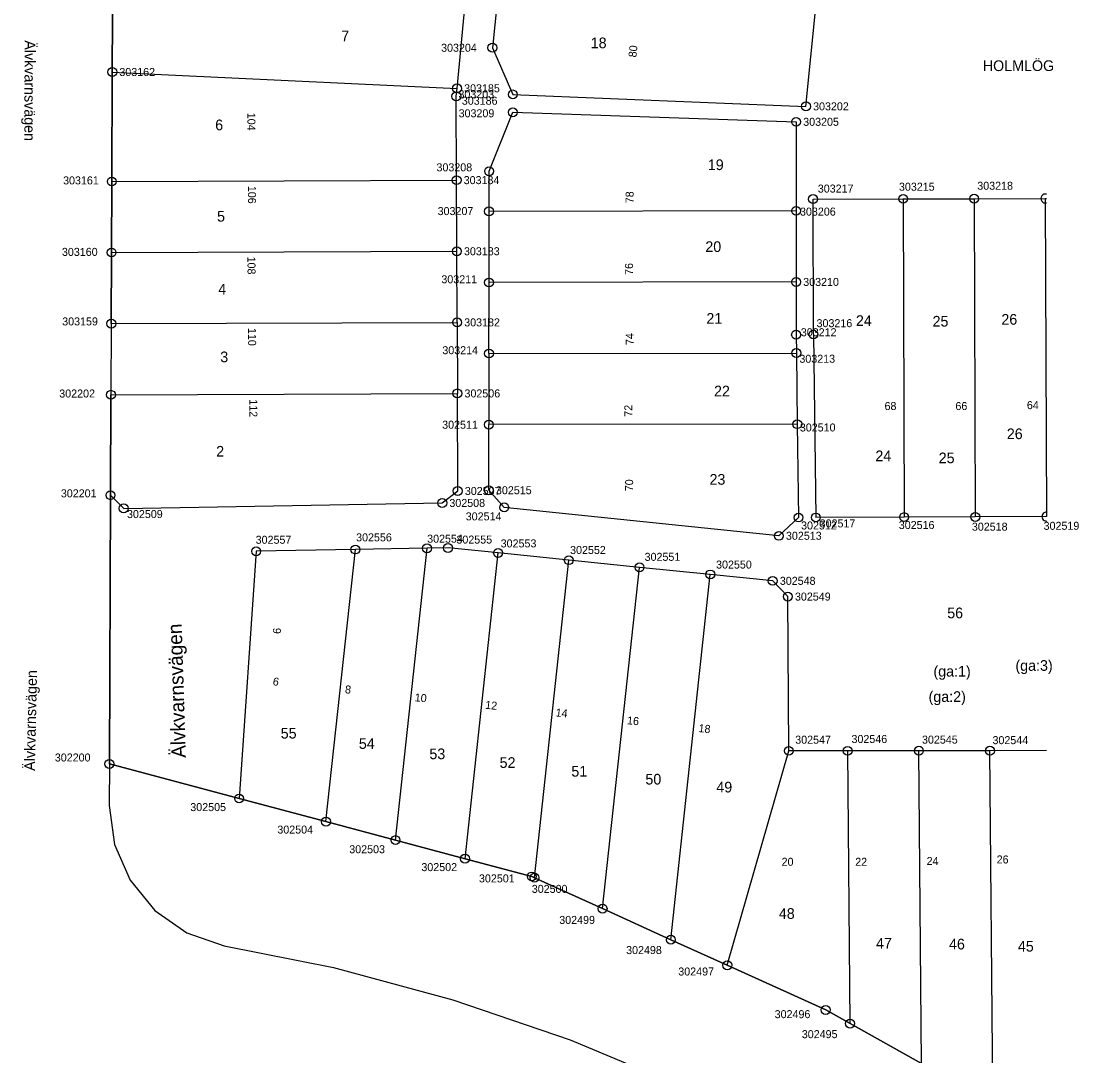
# Model space of a CAD drawing. Extents: x 141995 to 152570, y 6580184 to 6586000.
# Drawn here: x 142884.7 to 143003.6, y 6585368.8 to 6585485.2 of the extents above; entities that cross this region are included whole.
import ezdxf

# ---------------------------------------------------------------- set-up
doc = ezdxf.new("R2010")
doc.units = 0
for name, color, linetype in [('Level 10', 7, 'Continuous'), ('Level 13', 7, 'Continuous'), ('Level 40', 7, 'Continuous'), ('Level 42', 7, 'Continuous'), ('Level 43', 7, 'Continuous'), ('Level 5', 7, 'Continuous'), ('Level 50', 7, 'Continuous'), ('Level 51', 7, 'Continuous'), ('Level 53', 7, 'Continuous'), ('Level 54', 7, 'Continuous'), ('Level 55', 7, 'Continuous'), ('Level 59', 7, 'Continuous'), ('Level 6', 7, 'Continuous'), ('Level 7', 7, 'Continuous')]:
    doc.layers.add(name, color=color, linetype=linetype)

msp = doc.modelspace()

# ---------------------------------------------------------------- linework, layer by layer
at = {"layer": 'Level 10'}
for centre in [(142937.66, 6585482.19), (142894.9, 6585479.45), (142933.68, 6585477.61), (142939.96, 6585476.93), (142933.6, 6585476.72), (142939.96, 6585474.92), (142972.93, 6585475.59), (142971.82, 6585473.85), (142937.29, 6585468.29), (142894.85, 6585467.14), (142933.63, 6585467.29), (142973.73, 6585465.16), (142983.86, 6585465.19), (142991.85, 6585465.2), (142971.82, 6585463.84), (142937.28, 6585463.78), (142894.82, 6585459.15), (142933.66, 6585459.29), (142937.28, 6585455.78), (142971.82, 6585455.84), (142894.79, 6585451.15), (142933.69, 6585451.29), (142971.82, 6585449.91), (142973.77, 6585449.93), (142937.27, 6585447.79), (142971.85, 6585447.84), (142894.75, 6585443.15), (142933.72, 6585443.3), (142937.26, 6585439.79), (142971.95, 6585439.84), (142894.7, 6585431.85), (142933.76, 6585432.33), (142937.26, 6585432.41), (142932.02, 6585430.98), (142896.19, 6585430.37), (142938.99, 6585430.48), (142972.09, 6585429.34), (142974.04, 6585429.35), (142983.97, 6585429.39), (142991.97, 6585429.41), (142969.88, 6585427.28), (142922.25, 6585425.74), (142930.31, 6585425.88), (142932.67, 6585425.92), (142911.09, 6585425.54), (142938.3, 6585425.36), (142946.25, 6585424.54), (142954.21, 6585423.74), (142962.17, 6585422.94), (142969.19, 6585422.22), (142970.89, 6585420.45), (142971, 6585403.1), (142977.62, 6585403.1), (142985.63, 6585403.11), (142993.62, 6585403.11), (142894.58, 6585401.63), (142909.17, 6585397.74), (142918.94, 6585395.14), (142926.76, 6585393.06), (142934.58, 6585390.97), (142942.09, 6585388.97), (142942.39, 6585388.83), (142950.05, 6585385.35), (142957.73, 6585381.86), (142964.08, 6585378.98), (142975.15, 6585373.95), (142977.89, 6585372.42)]:
    msp.add_circle(centre, 0.5, dxfattribs=at)
for centre, start, end in [((142999.85, 6585465.23), 72.502, 287.498), ((142999.97, 6585429.44), 86.6662, 273.3338)]:
    msp.add_arc(centre, 0.5, start, end, dxfattribs=at)
at = {"layer": 'Level 13'}
for points in [[(142894.58, 6585401.63), (142894.56, 6585396.94)], [(142894.56, 6585396.94), (142895.15, 6585392.58)], [(142895.15, 6585392.58), (142896.9, 6585388.55)], [(142896.9, 6585388.55), (142899.68, 6585385.14)], [(142899.68, 6585385.14), (142903.29, 6585382.63)], [(142903.29, 6585382.63), (142907.48, 6585381.18)], [(142907.48, 6585381.18), (142919.78, 6585378.73)], [(142919.78, 6585378.73), (142933.21, 6585375.11)], [(142933.21, 6585375.11), (142946.39, 6585370.61)], [(142946.39, 6585370.61), (142959.22, 6585365.24)]]:
    msp.add_lwpolyline(points, dxfattribs=at)
at = {"layer": 'Level 5'}
for points in [[(142894.9, 6585479.45), (142894.95, 6585491.85)], [(142894.85, 6585467.14), (142894.9, 6585479.45)], [(142894.82, 6585459.15), (142894.85, 6585467.14)], [(142894.79, 6585451.15), (142894.82, 6585459.15)], [(142894.79, 6585451.15), (142894.75, 6585443.15)], [(142894.7, 6585431.85), (142894.75, 6585443.15)], [(142894.58, 6585401.63), (142894.7, 6585431.85)], [(142909.17, 6585397.74), (142894.58, 6585401.63)], [(142918.94, 6585395.14), (142909.17, 6585397.74)], [(142926.76, 6585393.06), (142918.94, 6585395.14)], [(142934.58, 6585390.97), (142926.76, 6585393.06)], [(142942.09, 6585388.97), (142934.58, 6585390.97)], [(142942.39, 6585388.83), (142942.09, 6585388.97)], [(142950.05, 6585385.35), (142942.39, 6585388.83)], [(142957.73, 6585381.86), (142950.05, 6585385.35)], [(142964.08, 6585378.98), (142957.73, 6585381.86)], [(142975.15, 6585373.95), (142964.08, 6585378.98)], [(142977.89, 6585372.42), (142975.15, 6585373.95)], [(142985.93, 6585367.95), (142977.89, 6585372.42)]]:
    msp.add_lwpolyline(points, dxfattribs=at)
at = {"layer": 'Level 6'}
msp.add_lwpolyline([(142894.95, 6585491.85), (142894.9, 6585479.45), (142894.85, 6585467.14), (142894.82, 6585459.15), (142894.79, 6585451.15), (142894.75, 6585443.15), (142894.7, 6585431.85), (142894.58, 6585401.63), (142909.17, 6585397.74), (142918.94, 6585395.14), (142926.76, 6585393.06), (142934.58, 6585390.97), (142942.09, 6585388.97), (142942.39, 6585388.83), (142950.05, 6585385.35), (142957.73, 6585381.86), (142964.08, 6585378.98), (142975.15, 6585373.95), (142977.89, 6585372.42), (142985.93, 6585367.95)], dxfattribs=at)
at = {"layer": 'Level 7'}
for points in [[(142938.49, 6585490.35), (142937.66, 6585482.19)], [(142933.68, 6585477.61), (142934.68, 6585487.93)], [(142972.93, 6585475.59), (142974.05, 6585486.74)], [(142937.66, 6585482.19), (142939.96, 6585476.93)], [(142894.9, 6585479.45), (142933.68, 6585477.61)], [(142933.6, 6585476.72), (142933.68, 6585477.61)], [(142933.63, 6585467.29), (142933.6, 6585476.72)], [(142939.96, 6585476.93), (142972.93, 6585475.59)], [(142937.29, 6585468.29), (142939.96, 6585474.92)], [(142939.96, 6585474.92), (142971.82, 6585473.85)], [(142971.82, 6585473.85), (142971.82, 6585463.84)], [(142937.28, 6585463.78), (142937.29, 6585468.29)], [(142894.85, 6585467.14), (142933.63, 6585467.29)], [(142933.66, 6585459.29), (142933.63, 6585467.29)], [(142973.73, 6585465.16), (142983.86, 6585465.19)], [(142973.77, 6585449.93), (142973.73, 6585465.16)], [(142983.86, 6585465.19), (142991.85, 6585465.2)], [(142983.86, 6585465.19), (142983.97, 6585429.39)], [(142991.85, 6585465.2), (142999.85, 6585465.23)], [(142991.85, 6585465.2), (142991.97, 6585429.41)], [(142999.85, 6585465.23), (142999.97, 6585429.44)], [(142999.85, 6585465.23), (143000, 6585465.23)], [(142971.82, 6585463.84), (142937.28, 6585463.78)], [(142937.28, 6585455.78), (142937.28, 6585463.78)], [(142971.82, 6585463.84), (142971.82, 6585455.84)], [(142894.82, 6585459.15), (142933.66, 6585459.29)], [(142933.69, 6585451.29), (142933.66, 6585459.29)], [(142937.27, 6585447.79), (142937.28, 6585455.78)], [(142971.82, 6585455.84), (142937.28, 6585455.78)], [(142971.82, 6585455.84), (142971.82, 6585449.91)], [(142894.79, 6585451.15), (142933.69, 6585451.29)], [(142933.69, 6585451.29), (142933.72, 6585443.3)], [(142971.82, 6585449.91), (142971.85, 6585447.84)], [(142973.77, 6585449.93), (142974.04, 6585429.35)], [(142937.27, 6585447.79), (142937.26, 6585439.79)], [(142937.27, 6585447.79), (142971.85, 6585447.84)], [(142971.85, 6585447.84), (142971.95, 6585439.84)], [(142894.75, 6585443.15), (142933.72, 6585443.3)], [(142933.76, 6585432.33), (142933.72, 6585443.3)], [(142971.95, 6585439.84), (142937.26, 6585439.79)], [(142937.26, 6585432.41), (142937.26, 6585439.79)], [(142971.95, 6585439.84), (142972.09, 6585429.34)], [(142932.02, 6585430.98), (142933.76, 6585432.33)], [(142938.99, 6585430.48), (142937.26, 6585432.41)], [(142894.7, 6585431.85), (142896.19, 6585430.37)], [(142896.19, 6585430.37), (142932.02, 6585430.98)], [(142969.88, 6585427.28), (142938.99, 6585430.48)], [(142972.09, 6585429.34), (142969.88, 6585427.28)], [(142983.97, 6585429.39), (142974.04, 6585429.35)], [(142991.97, 6585429.41), (142983.97, 6585429.39)], [(142999.97, 6585429.44), (142991.97, 6585429.41)], [(143000, 6585429.44), (142999.97, 6585429.44)], [(142911.09, 6585425.54), (142909.17, 6585397.74)], [(142922.25, 6585425.74), (142911.09, 6585425.54)], [(142918.94, 6585395.14), (142922.25, 6585425.74)], [(142930.31, 6585425.88), (142922.25, 6585425.74)], [(142926.76, 6585393.06), (142930.31, 6585425.88)], [(142932.67, 6585425.92), (142930.31, 6585425.88)], [(142938.3, 6585425.36), (142932.67, 6585425.92)], [(142934.58, 6585390.97), (142938.3, 6585425.36)], [(142946.25, 6585424.54), (142938.3, 6585425.36)], [(142942.39, 6585388.83), (142946.25, 6585424.54)], [(142954.21, 6585423.74), (142946.25, 6585424.54)], [(142950.05, 6585385.35), (142954.21, 6585423.74)], [(142962.17, 6585422.94), (142954.21, 6585423.74)], [(142957.73, 6585381.86), (142962.17, 6585422.94)], [(142969.19, 6585422.22), (142962.17, 6585422.94)], [(142970.89, 6585420.45), (142969.19, 6585422.22)], [(142971, 6585403.1), (142970.89, 6585420.45)], [(142964.08, 6585378.98), (142971, 6585403.1)], [(142977.62, 6585403.1), (142971, 6585403.1)], [(142985.63, 6585403.11), (142977.62, 6585403.1)], [(142977.89, 6585372.42), (142977.62, 6585403.1)], [(142985.93, 6585367.95), (142985.63, 6585403.11)], [(142993.62, 6585403.11), (142985.63, 6585403.11)], [(143000, 6585403.12), (142993.62, 6585403.11)], [(142993.94, 6585364.99), (142993.62, 6585403.11)]]:
    msp.add_lwpolyline(points, dxfattribs=at)

# ---------------------------------------------------------------- texts
at = {"layer": 'Level 40'}
msp.add_text('Älvkvarnsvägen', height=1.2, rotation=88.766, dxfattribs=at).set_placement((142886.2, 6585400.84))
at = {"layer": 'Level 42'}
msp.add_text('Älvkvarnsvägen', height=1.2, rotation=269.7781, dxfattribs=at).set_placement((142885.05, 6585483.02))
at = {"layer": 'Level 43'}
msp.add_text('Älvkvarnsvägen', height=1.6, rotation=91.766, dxfattribs=at).set_placement((142903.18, 6585402.33))
at = {"layer": 'Level 50'}
msp.add_text('HOLMLÖG', height=1.2, rotation=0.049, dxfattribs=at).set_placement((142992.82, 6585479.56))
at = {"layer": 'Level 51'}
for s, rotation, p in [('7', 0.049, (142920.66, 6585482.91)), ('18', 0.049, (142948.72, 6585482.13)), ('6', 0.049, (142906.48, 6585472.9)), ('19', 0.049, (142961.89, 6585468.42)), ('5', 0.049, (142906.69, 6585462.62)), ('20', 0.049, (142961.61, 6585459.21)), ('4', 0.049, (142906.82, 6585454.42)), ('21', 0.049, (142961.73, 6585451.14)), ('24', 0.049, (142978.55, 6585450.89)), ('25', 0.049, (142987.17, 6585450.82)), ('26', 0.049, (142994.91, 6585451.03)), ('3', 0.049, (142907.05, 6585446.81)), ('22', 0.049, (142962.59, 6585442.97)), ('2', 0.049, (142906.59, 6585436.19)), ('23', 0.049, (142962.08, 6585433.03)), ('56', 0.049, (142988.82, 6585418.01)), ('(ga:1)', 0.0493, (142987.27, 6585411.45)), ('55', 0.0493, (142913.85, 6585404.48)), ('54', 0.0493, (142922.64, 6585403.32)), ('53', 0.0493, (142930.57, 6585402.16)), ('52', 0.0493, (142938.47, 6585401.18)), ('51', 0.0493, (142946.54, 6585400.2)), ('50', 0.0493, (142954.87, 6585399.31)), ('49', 0.0493, (142962.85, 6585398.42)), ('48', 0.0493, (142969.88, 6585384.2)), ('47', 0.0493, (142980.81, 6585380.85)), ('46', 0.0493, (142989.02, 6585380.76)), ('45', 0.0493, (142996.77, 6585380.52))]:
    msp.add_text(s, height=1.2, rotation=rotation, dxfattribs=at).set_placement(p)
for s, p in [('(ga:3)', (142996.49, 6585412.1)), ('(ga:2)', (142986.72, 6585408.6))]:
    msp.add_text(s, height=1.2, dxfattribs=at).set_placement(p)
at = {"layer": 'Level 53'}
for s, rotation, p in [('303204', 0.049, (142931.89, 6585481.73)), ('303162', 0.049, (142895.7, 6585479)), ('303203', 0.049, (142933.84, 6585476.51)), ('303185', 0.049, (142934.48, 6585477.17)), ('303186', 0.049, (142934.22, 6585475.77)), ('303209', 0.049, (142933.86, 6585474.36)), ('303202', 0.049, (142973.73, 6585475.14)), ('303205', 0.049, (142972.62, 6585473.4)), ('303208', 0.049, (142931.37, 6585468.28)), ('303161', 0.049, (142889.37, 6585466.81)), ('303184', 0.049, (142934.43, 6585466.84)), ('303217', 0.049, (142974.26, 6585465.89)), ('303215', 0.049, (142983.39, 6585466.1)), ('303218', 0.049, (142992.2, 6585466.21)), ('303207', 0.049, (142931.5, 6585463.36)), ('303206', 0.049, (142972.26, 6585463.3)), ('303160', 0.049, (142889.24, 6585458.77)), ('303183', 0.049, (142934.46, 6585458.84)), ('303211', 0.049, (142931.92, 6585455.69)), ('303210', 0.049, (142972.62, 6585455.39)), ('303159', 0.049, (142889.27, 6585450.95)), ('303182', 0.049, (142934.49, 6585450.84)), ('303216', 0.049, (142974.12, 6585450.75)), ('303212', 0.049, (142972.35, 6585449.73)), ('303214', 0.049, (142932.03, 6585447.71)), ('303213', 0.049, (142972.19, 6585446.75)), ('302202', 0.049, (142888.94, 6585442.84)), ('302506', 0.049, (142934.52, 6585442.85)), ('302511', 0.049, (142932.01, 6585439.33)), ('302510', 0.049, (142972.24, 6585439.02)), ('302201', 0.049, (142889.12, 6585431.61)), ('302507', 0.049, (142934.56, 6585431.88)), ('302515', 0.049, (142938.06, 6585431.96)), ('302508', 0.049, (142932.82, 6585430.53)), ('302509', 0.049, (142896.56, 6585429.28)), ('302514', 0.049, (142934.66, 6585429.02)), ('302512', 0.049, (142972.38, 6585428)), ('302517', 0.049, (142974.47, 6585428.23)), ('302516', 0.049, (142983.37, 6585428.05)), ('302518', 0.049, (142991.59, 6585427.86)), ('302519', 0.049, (142999.66, 6585427.96)), ('302556', 0.049, (142922.33, 6585426.66)), ('302513', 0.049, (142970.68, 6585426.84)), ('302557', 0.049, (142911.03, 6585426.39)), ('302554', 0.049, (142930.32, 6585426.51)), ('302555', 0.049, (142933.61, 6585426.41)), ('302553', 0.049, (142938.59, 6585425.98)), ('302552', 0.049, (142946.4, 6585425.24)), ('302551', 0.049, (142954.78, 6585424.47)), ('302550', 0.049, (142962.82, 6585423.6)), ('302548', 0.049, (142969.99, 6585421.77)), ('302549', 0.049, (142971.69, 6585420)), ('302546', 0.0493, (142978.05, 6585403.98)), ('302545', 0.0493, (142985.98, 6585403.91)), ('302547', 0.0493, (142971.72, 6585403.9)), ('302544', 0.0493, (142993.91, 6585403.85)), ('302200', 0.0493, (142888.44, 6585401.9)), ('302505', 0.0493, (142903.68, 6585396.32)), ('302504', 0.0493, (142913.47, 6585393.79)), ('302503', 0.0493, (142921.56, 6585391.58)), ('302502', 0.0493, (142929.67, 6585389.57)), ('302501', 0.0493, (142936.15, 6585388.3)), ('302500', 0.0493, (142942.09, 6585387.12)), ('302499', 0.0493, (142945.18, 6585383.63)), ('302498', 0.0493, (142952.7, 6585380.24)), ('302497', 0.0493, (142958.57, 6585377.83)), ('302496', 0.0493, (142969.41, 6585373.03)), ('302495', 0.0493, (142972.46, 6585370.78))]:
    msp.add_text(s, height=0.9, rotation=rotation, dxfattribs=at).set_placement(p)
at = {"layer": 'Level 54'}
for s, rotation, p in [('80', 84.3053, (142953.85, 6585481.07)), ('104', 270.183, (142910.1, 6585474.87)), ('106', 270.183, (142910.17, 6585466.65)), ('78', 89.9231, (142953.54, 6585464.69)), ('108', 270.183, (142910.11, 6585458.69)), ('76', 90.026, (142953.47, 6585456.63)), ('110', 270.183, (142910.18, 6585450.66)), ('74', 89.9071, (142953.56, 6585448.74)), ('112', 270.186, (142910.32, 6585442.64)), ('72', 89.9741, (142953.4, 6585440.68)), ('68', 0.222, (142981.77, 6585441.43)), ('66', 0.192, (142989.74, 6585441.43)), ('64', 0.192, (142997.78, 6585441.53)), ('70', 89.9721, (142953.49, 6585432.3)), ('6', 349.0495, (142912.9, 6585410.51)), ('8', 353.2077, (142921.04, 6585409.59)), ('10', 354.5778, (142928.89, 6585408.68)), ('12', 354.1603, (142936.82, 6585407.84)), ('14', 354.2393, (142944.74, 6585406.98)), ('16', 354.2393, (142952.77, 6585406.1)), ('18', 354.1923, (142960.81, 6585405.22)), ('20', 0.0493, (142970.19, 6585390.17)), ('22', 0.0493, (142978.47, 6585390.17)), ('24', 0.0493, (142986.5, 6585390.26)), ('26', 0.0493, (142994.38, 6585390.43))]:
    msp.add_text(s, height=0.9, rotation=rotation, dxfattribs=at).set_placement(p)
at = {"layer": 'Level 55'}
msp.add_text('6', height=0.9, rotation=86.0582, dxfattribs=at).set_placement((142913.85, 6585416.23))
at = {"layer": 'Level 59'}
for s, p in [('26', (142995.52, 6585438.16)), ('24', (142980.74, 6585435.68)), ('25', (142987.86, 6585435.45))]:
    msp.add_text(s, height=1.2, rotation=0.049, dxfattribs=at).set_placement(p)

doc.saveas('drawing.dxf')
